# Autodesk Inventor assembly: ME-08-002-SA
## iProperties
Shininess: 20.0
Length Units: 11269
Angle Units: 11279
Time Units: 11290
Mass Units: 11283
Length Display Precision: 3
Angle Display Precision: 2
Created: 2001-04
Part Number: ME-08-002-SA
Document SubType Name: Baugruppe
Designer: dl
Density: 0.0
Volumn: 0.0
Area: 0.0
PropertySet Name: Model Information
Control State: 0
Master: False
Checked Out: False
Author: dl
